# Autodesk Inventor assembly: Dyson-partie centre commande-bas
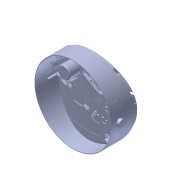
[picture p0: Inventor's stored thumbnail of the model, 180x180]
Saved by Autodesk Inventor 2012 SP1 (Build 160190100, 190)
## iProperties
Created: 2012-11
Part Number: Dyson-partie centre commande-bas
Document SubType Name: Assembly
Designer: Administrateur
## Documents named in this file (7)
- D:\Cours\1-Cours-2013-14\Dropbox\1SI\1. Besoin\Dyson\Composants importés\Dyson Air Multiplier-Assemblage final\Dyson-partie centre commande-bas.iam
- D:\Cours\1-Cours-2013-14\Dropbox\1SI\1. Besoin\Dyson\Composants importés\Dyson Air Multiplier-Assemblage final\Dyson-Partie centre commande.ipt
- D:\Cours\1-Cours-2013-14\Dropbox\1SI\1. Besoin\Dyson\Composants importés\Dyson Air Multiplier-Assemblage final\Dyson-Partie centre support commande.ipt
- D:\Cours\1-Cours-2013-14\Dropbox\1SI\1. Besoin\Dyson\Composants importés\Dyson Air Multiplier-Assemblage final\Vis torks M2x6.ipt
- D:\Cours\1-Cours-2013-14\Dropbox\1SI\1. Besoin\Dyson\Composants importés\Dyson Air Multiplier-Assemblage final\Dyson-Partie centre Ci commande.ipt
- D:\Cours\1-Cours-2013-14\Dropbox\1SI\1. Besoin\Dyson\Composants importés\Dyson Air Multiplier-Assemblage final\Dyson-Partie centre liaison.ipt
- D:\Cours\1-Cours-2013-14\Dropbox\1SI\1. Besoin\Dyson\Composants importés\Dyson Air Multiplier-Assemblage final\Dyson-partie centre motorisation.iam
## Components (10 placed, 6 different names)
1. Dyson-Partie centre commande:1
2. Dyson-Partie centre support commande:1
3. Vis torks M2x6:1
4. Vis torks M2x6:2
5. Dyson-Partie centre Ci commande:1
6. Vis torks M2x6:3
7. Vis torks M2x6:4
8. Vis torks M2x6:5
9. Dyson-Partie centre liaison:1
10. Dyson-partie centre motorisation:1 [sub-assembly]
